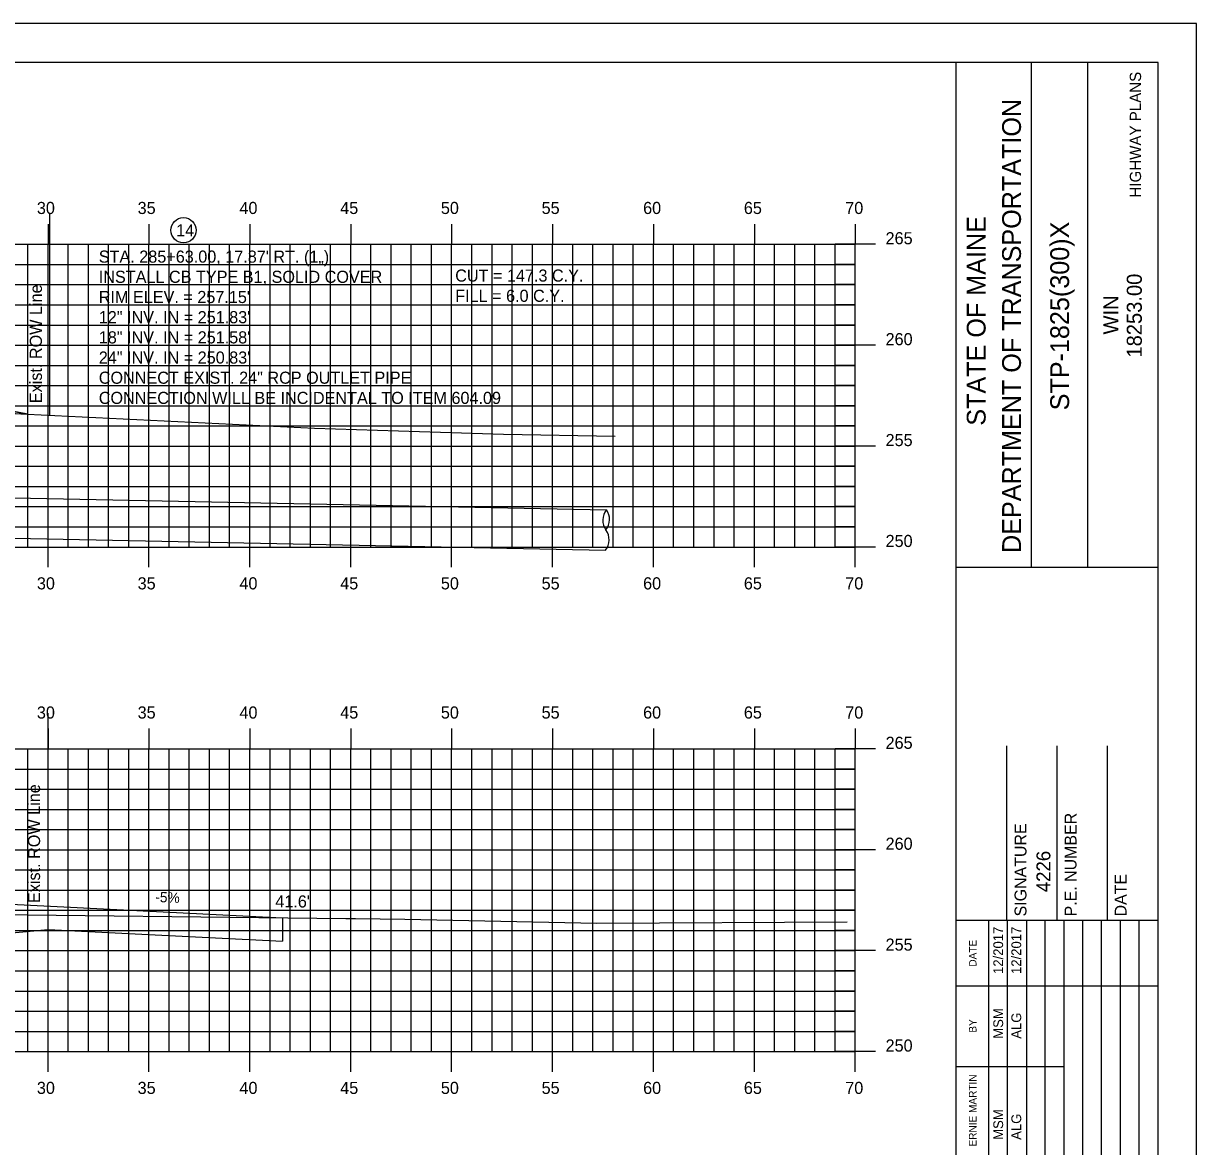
# Model space of a CAD drawing. Extents: x 856680 to 856850, y 366268 to 366378.
# Drawn here: x 856791.9 to 856850, y 366322.5 to 366378.2 of the extents above; entities that cross this region are included whole.
import ezdxf

# ---------------------------------------------------------------- set-up
doc = ezdxf.new("R2010")
doc.units = 0
for name, color, linetype in [('ANNOTATION', 7, 'Continuous'), ('BORDER', 7, 'Continuous'), ('D_Drainage_Text', 7, 'Continuous'), ('D_Roadway_Drive_Gravel_RT', 7, 'Continuous'), ('D_Roadway_Drive_SubGrade', 7, 'Continuous'), ('D_Roadway_FinishedGrade', 7, 'Continuous'), ('D_Text_Standard', 7, 'Continuous'), ('E_ROW_Line', 7, 'Continuous'), ('H_V ANNOTATION', 7, 'Continuous'), ('HIGHWAY_TITLE', 7, 'Continuous'), ('JUNK FILL', 7, 'Continuous'), ('MAJOR', 7, 'Continuous'), ('MINOR', 7, 'Continuous'), ('PLOT BOUNDARY', 7, 'Continuous'), ('S_Drainage_Culvert_Top', 7, 'Continuous'), ('S_Roadway_Centerline', 7, 'Continuous')]:
    doc.layers.add(name, color=color, linetype=linetype)

msp = doc.modelspace()

# ---------------------------------------------------------------- linework, layer by layer
at = {"layer": 'BORDER'}
for p, q in [((856848.116, 366376.236), (856688.116, 366376.236)), ((856838.116, 366271.236), (856838.116, 366376.239)), ((856841.845, 366351.234), (856841.845, 366376.234)), ((856844.64, 366351.234), (856844.64, 366376.234)), ((856848.116, 366271.236), (856848.116, 366376.236)), ((856838.117, 366351.231), (856848.116, 366351.231)), ((856840.616, 366333.739), (856840.616, 366342.387)), ((856843.116, 366333.739), (856843.116, 366342.387)), ((856845.616, 366333.739), (856845.616, 366342.387)), ((856838.116, 366333.739), (856848.116, 366333.739))]:
    msp.add_line(p, q, dxfattribs=at)
for points in [[(856839.731, 366330.489), (856839.731, 366333.739)], [(856840.664, 366316.242), (856840.664, 366333.739)], [(856841.596, 366333.739), (856841.596, 366316.242)], [(856842.527, 366316.242), (856842.527, 366333.739)], [(856843.459, 366316.242), (856843.459, 366333.739)], [(856844.391, 366316.242), (856844.391, 366333.739)], [(856845.322, 366316.242), (856845.322, 366333.739)], [(856846.254, 366316.242), (856846.254, 366333.739)], [(856847.186, 366316.242), (856847.186, 366333.739)], [(856839.732, 366316.242), (856839.732, 366333.033)], [(856838.116, 366330.489), (856848.116, 366330.489)], [(856838.116, 366326.489), (856839.732, 366326.489)], [(856839.731, 366326.489), (856843.458, 366326.489)]]:
    msp.add_lwpolyline(points, dxfattribs=at)
at = {"layer": 'D_Drainage_Text'}
msp.add_circle((856799.831, 366367.931), 0.625, dxfattribs=at)
at = {"layer": 'D_Roadway_Drive_Gravel_RT'}
for p, q in [((856787.117, 366334.751), (856804.736, 366333.87)), ((856793.116, 366333.283), (856804.736, 366332.702))]:
    msp.add_line(p, q, dxfattribs=at)
at = {"layer": 'D_Roadway_Drive_SubGrade'}
for p, q in [((856804.736, 366333.87), (856804.736, 366332.703)), ((856783.116, 366332.397), (856793.116, 366333.283))]:
    msp.add_line(p, q, dxfattribs=at)
at = {"layer": 'D_Roadway_FinishedGrade'}
msp.add_lwpolyline([(856785.533, 366360.081), (856792.116, 366358.816)], dxfattribs=at)
at = {"layer": 'E_ROW_Line'}
for p, q in [((856793.214, 366358.763), (856793.214, 366368.763)), ((856793.123, 366333.997), (856793.123, 366343.997))]:
    msp.add_line(p, q, dxfattribs=at)
at = {"layer": 'JUNK FILL'}
msp.add_lwpolyline([(856783.116, 366360.13), (856783.116, 366358.735), (856783.824, 366358.804), (856784.545, 366358.884), (856786.381, 366359.268), (856788.154, 366359.038), (856788.771, 366359.002), (856792.116, 366358.816), (856785.533, 366360.081)], close=True, dxfattribs=at)
at = {"layer": 'MAJOR'}
for p, q in [((856793.116, 366368.238), (856793.116, 366367.236)), ((856798.116, 366368.238), (856798.116, 366367.236)), ((856803.116, 366368.238), (856803.116, 366367.236)), ((856808.116, 366368.238), (856808.116, 366367.236)), ((856813.116, 366368.238), (856813.116, 366367.236)), ((856818.116, 366368.238), (856818.116, 366367.236)), ((856823.116, 366368.238), (856823.116, 366367.236)), ((856828.116, 366368.238), (856828.116, 366367.236)), ((856833.116, 366368.238), (856833.116, 366367.236)), ((856693.116, 366367.236), (856833.116, 366367.236)), ((856693.116, 366367.236), (856833.116, 366367.236)), ((856793.116, 366352.236), (856793.116, 366367.236)), ((856798.116, 366352.236), (856798.116, 366367.236)), ((856803.116, 366352.236), (856803.116, 366367.236)), ((856808.116, 366352.236), (856808.116, 366367.236)), ((856813.116, 366352.236), (856813.116, 366367.236)), ((856818.116, 366352.236), (856818.116, 366367.236)), ((856823.116, 366352.236), (856823.116, 366367.236)), ((856828.116, 366352.236), (856828.116, 366367.236)), ((856834.118, 366367.236), (856832.114, 366367.236)), ((856833.116, 366352.236), (856833.116, 366367.236)), ((856833.116, 366352.236), (856833.116, 366367.236)), ((856693.116, 366362.236), (856833.116, 366362.236)), ((856834.118, 366362.236), (856832.114, 366362.236)), ((856693.116, 366357.236), (856833.116, 366357.236)), ((856834.118, 366357.236), (856832.114, 366357.236)), ((856693.116, 366352.236), (856833.116, 366352.236)), ((856693.116, 366352.236), (856833.116, 366352.236)), ((856793.116, 366351.234), (856793.116, 366352.236)), ((856798.116, 366351.234), (856798.116, 366352.236)), ((856803.116, 366351.234), (856803.116, 366352.236)), ((856808.116, 366351.234), (856808.116, 366352.236)), ((856813.116, 366351.234), (856813.116, 366352.236)), ((856818.116, 366351.234), (856818.116, 366352.236)), ((856823.116, 366351.234), (856823.116, 366352.236)), ((856828.116, 366351.234), (856828.116, 366352.236)), ((856834.118, 366352.236), (856832.114, 366352.236)), ((856833.116, 366351.234), (856833.116, 366352.236)), ((856793.116, 366343.238), (856793.116, 366342.236)), ((856798.116, 366343.238), (856798.116, 366342.236)), ((856803.116, 366343.238), (856803.116, 366342.236)), ((856808.116, 366343.238), (856808.116, 366342.236)), ((856813.116, 366343.238), (856813.116, 366342.236)), ((856818.116, 366343.238), (856818.116, 366342.236)), ((856823.116, 366343.238), (856823.116, 366342.236)), ((856828.116, 366343.238), (856828.116, 366342.236)), ((856833.116, 366343.238), (856833.116, 366342.236)), ((856693.116, 366342.236), (856833.116, 366342.236)), ((856693.116, 366342.236), (856833.116, 366342.236)), ((856793.116, 366327.236), (856793.116, 366342.236)), ((856798.116, 366327.236), (856798.116, 366342.236)), ((856803.116, 366327.236), (856803.116, 366342.236)), ((856808.116, 366327.236), (856808.116, 366342.236)), ((856813.116, 366327.236), (856813.116, 366342.236)), ((856818.116, 366327.236), (856818.116, 366342.236)), ((856823.116, 366327.236), (856823.116, 366342.236)), ((856828.116, 366327.236), (856828.116, 366342.236)), ((856834.118, 366342.236), (856832.114, 366342.236)), ((856833.116, 366327.236), (856833.116, 366342.236)), ((856833.116, 366327.236), (856833.116, 366342.236)), ((856693.116, 366337.236), (856833.116, 366337.236)), ((856834.118, 366337.236), (856832.114, 366337.236)), ((856693.116, 366332.236), (856833.116, 366332.236)), ((856834.118, 366332.236), (856832.114, 366332.236)), ((856693.116, 366327.236), (856833.116, 366327.236)), ((856693.116, 366327.236), (856833.116, 366327.236)), ((856793.116, 366326.234), (856793.116, 366327.236)), ((856798.116, 366326.234), (856798.116, 366327.236)), ((856803.116, 366326.234), (856803.116, 366327.236)), ((856808.116, 366326.234), (856808.116, 366327.236)), ((856813.116, 366326.234), (856813.116, 366327.236)), ((856818.116, 366326.234), (856818.116, 366327.236)), ((856823.116, 366326.234), (856823.116, 366327.236)), ((856828.116, 366326.234), (856828.116, 366327.236)), ((856834.118, 366327.236), (856832.114, 366327.236)), ((856833.116, 366326.234), (856833.116, 366327.236))]:
    msp.add_line(p, q, dxfattribs=at)
at = {"layer": 'MINOR'}
for p, q in [((856792.116, 366352.236), (856792.116, 366367.236)), ((856794.116, 366352.236), (856794.116, 366367.236)), ((856795.116, 366352.236), (856795.116, 366367.236)), ((856796.116, 366352.236), (856796.116, 366367.236)), ((856797.116, 366352.236), (856797.116, 366367.236)), ((856799.116, 366352.236), (856799.116, 366367.236)), ((856800.116, 366352.236), (856800.116, 366367.236)), ((856801.116, 366352.236), (856801.116, 366367.236)), ((856802.116, 366352.236), (856802.116, 366367.236)), ((856804.116, 366352.236), (856804.116, 366367.236)), ((856805.116, 366352.236), (856805.116, 366367.236)), ((856806.116, 366352.236), (856806.116, 366367.236)), ((856807.116, 366352.236), (856807.116, 366367.236)), ((856809.116, 366352.236), (856809.116, 366367.236)), ((856810.116, 366352.236), (856810.116, 366367.236)), ((856811.116, 366352.236), (856811.116, 366367.236)), ((856812.116, 366352.236), (856812.116, 366367.236)), ((856814.116, 366352.236), (856814.116, 366367.236)), ((856815.116, 366352.236), (856815.116, 366367.236)), ((856816.116, 366352.236), (856816.116, 366367.236)), ((856817.116, 366352.236), (856817.116, 366367.236)), ((856819.116, 366352.236), (856819.116, 366367.236)), ((856820.116, 366352.236), (856820.116, 366367.236)), ((856821.116, 366352.236), (856821.116, 366367.236)), ((856822.116, 366352.236), (856822.116, 366367.236)), ((856824.116, 366352.236), (856824.116, 366367.236)), ((856825.116, 366352.236), (856825.116, 366367.236)), ((856826.116, 366352.236), (856826.116, 366367.236)), ((856827.116, 366352.236), (856827.116, 366367.236)), ((856829.116, 366352.236), (856829.116, 366367.236)), ((856830.116, 366352.236), (856830.116, 366367.236)), ((856831.116, 366352.236), (856831.116, 366367.236)), ((856832.116, 366352.236), (856832.116, 366367.236)), ((856693.116, 366366.236), (856833.116, 366366.236)), ((856833.116, 366366.236), (856832.114, 366366.236)), ((856693.116, 366365.236), (856833.116, 366365.236)), ((856833.116, 366365.236), (856832.114, 366365.236)), ((856693.116, 366364.236), (856833.116, 366364.236)), ((856833.116, 366364.236), (856832.114, 366364.236)), ((856693.116, 366363.236), (856833.116, 366363.236)), ((856833.116, 366363.236), (856832.114, 366363.236)), ((856693.116, 366361.236), (856833.116, 366361.236)), ((856833.116, 366361.236), (856832.114, 366361.236)), ((856693.116, 366360.236), (856833.116, 366360.236)), ((856833.116, 366360.236), (856832.114, 366360.236)), ((856693.116, 366359.236), (856833.116, 366359.236)), ((856833.116, 366359.236), (856832.114, 366359.236)), ((856693.116, 366358.236), (856833.116, 366358.236)), ((856833.116, 366358.236), (856832.114, 366358.236)), ((856693.116, 366356.236), (856833.116, 366356.236)), ((856833.116, 366356.236), (856832.114, 366356.236)), ((856693.116, 366355.236), (856833.116, 366355.236)), ((856833.116, 366355.236), (856832.114, 366355.236)), ((856693.116, 366354.236), (856833.116, 366354.236)), ((856833.116, 366354.236), (856832.114, 366354.236)), ((856693.116, 366353.236), (856833.116, 366353.236)), ((856833.116, 366353.236), (856832.114, 366353.236)), ((856792.116, 366327.236), (856792.116, 366342.236)), ((856794.116, 366327.236), (856794.116, 366342.236)), ((856795.116, 366327.236), (856795.116, 366342.236)), ((856796.116, 366327.236), (856796.116, 366342.236)), ((856797.116, 366327.236), (856797.116, 366342.236)), ((856799.116, 366327.236), (856799.116, 366342.236)), ((856800.116, 366327.236), (856800.116, 366342.236)), ((856801.116, 366327.236), (856801.116, 366342.236)), ((856802.116, 366327.236), (856802.116, 366342.236)), ((856804.116, 366327.236), (856804.116, 366342.236)), ((856805.116, 366327.236), (856805.116, 366342.236)), ((856806.116, 366327.236), (856806.116, 366342.236)), ((856807.116, 366327.236), (856807.116, 366342.236)), ((856809.116, 366327.236), (856809.116, 366342.236)), ((856810.116, 366327.236), (856810.116, 366342.236)), ((856811.116, 366327.236), (856811.116, 366342.236)), ((856812.116, 366327.236), (856812.116, 366342.236)), ((856814.116, 366327.236), (856814.116, 366342.236)), ((856815.116, 366327.236), (856815.116, 366342.236)), ((856816.116, 366327.236), (856816.116, 366342.236)), ((856817.116, 366327.236), (856817.116, 366342.236)), ((856819.116, 366327.236), (856819.116, 366342.236)), ((856820.116, 366327.236), (856820.116, 366342.236)), ((856821.116, 366327.236), (856821.116, 366342.236)), ((856822.116, 366327.236), (856822.116, 366342.236)), ((856824.116, 366327.236), (856824.116, 366342.236)), ((856825.116, 366327.236), (856825.116, 366342.236)), ((856826.116, 366327.236), (856826.116, 366342.236)), ((856827.116, 366327.236), (856827.116, 366342.236)), ((856829.116, 366327.236), (856829.116, 366342.236)), ((856830.116, 366327.236), (856830.116, 366342.236)), ((856831.116, 366327.236), (856831.116, 366342.236)), ((856832.116, 366327.236), (856832.116, 366342.236)), ((856693.116, 366341.236), (856833.116, 366341.236)), ((856833.116, 366341.236), (856832.114, 366341.236)), ((856693.116, 366340.236), (856833.116, 366340.236)), ((856833.116, 366340.236), (856832.114, 366340.236)), ((856693.116, 366339.236), (856833.116, 366339.236)), ((856833.116, 366339.236), (856832.114, 366339.236)), ((856693.116, 366338.236), (856833.116, 366338.236)), ((856833.116, 366338.236), (856832.114, 366338.236)), ((856693.116, 366336.236), (856833.116, 366336.236)), ((856833.116, 366336.236), (856832.114, 366336.236)), ((856693.116, 366335.236), (856833.116, 366335.236)), ((856833.116, 366335.236), (856832.114, 366335.236)), ((856693.116, 366334.236), (856833.116, 366334.236)), ((856833.116, 366334.236), (856832.114, 366334.236)), ((856693.116, 366333.236), (856833.116, 366333.236)), ((856833.116, 366333.236), (856832.114, 366333.236)), ((856693.116, 366331.236), (856833.116, 366331.236)), ((856833.116, 366331.236), (856832.114, 366331.236)), ((856693.116, 366330.236), (856833.116, 366330.236)), ((856833.116, 366330.236), (856832.114, 366330.236)), ((856693.116, 366329.236), (856833.116, 366329.236)), ((856833.116, 366329.236), (856832.114, 366329.236)), ((856693.116, 366328.236), (856833.116, 366328.236)), ((856833.116, 366328.236), (856832.114, 366328.236))]:
    msp.add_line(p, q, dxfattribs=at)
at = {"layer": 'PLOT BOUNDARY'}
msp.add_lwpolyline([(856680.023, 366268.177), (856850.023, 366268.177), (856850.023, 366378.177), (856680.023, 366378.177)], close=True, dxfattribs=at)
at = {"layer": 'S_Drainage_Culvert_Top'}
for p, q in [((856783.873, 366354.819), (856820.78, 366354.081)), ((856783.873, 366352.818), (856820.74, 366352.081))]:
    msp.add_line(p, q, dxfattribs=at)
for centre, start, end in [((856821.437, 366353.567), 141.98434, 215.72413), ((856820.104, 366353.594), 321.98434, 35.72413), ((856820.084, 366352.594), 321.98434, 35.72413)]:
    msp.add_arc(centre, 0.833, start, end, dxfattribs=at)
at = {"layer": 'S_Roadway_Centerline'}
for points in [[(856791.431, 366358.849), (856806.317, 366358.133), (856815.684, 366357.834), (856821.222, 366357.728)], [(856787.76, 366334.057), (856807.868, 366333.829), (856808.093, 366333.826), (856808.204, 366333.826), (856808.258, 366333.826), (856808.306, 366333.826), (856808.328, 366333.826), (856808.353, 366333.826), (856810.804, 366333.794), (856820.314, 366333.599), (856832.717, 366333.667)]]:
    msp.add_lwpolyline(points, dxfattribs=at)

# ---------------------------------------------------------------- texts
at = {"layer": 'ANNOTATION'}
for s, p in [('CUT = 147.3 C.Y.', (856813.292, 366365.386)), ('FILL = 6.0 C.Y.', (856813.292, 366364.384))]:
    msp.add_text(s, height=0.6, dxfattribs=at).set_placement(p)
for s, height, rotation, p in [('4226', 0.69, 90, (856842.781, 366335.13)), ('-5%', 0.51, 357.70939, (856798.422, 366334.648))]:
    msp.add_text(s, height=height, rotation=rotation, dxfattribs=at).set_placement(p)
at = {"layer": 'BORDER'}
for s, height, p in [('DEPARTMENT OF TRANSPORTATION', 0.93176, (856841.323, 366351.942)), ('STATE OF MAINE', 0.93176, (856839.572, 366358.248)), ('STP-1825(300)X', 0.93176, (856843.708, 366359.008)), ('18253.00', 0.7453, (856847.312, 366361.623)), ('WIN', 0.7453, (856846.153, 366362.766)), ('P.E. NUMBER', 0.59055, (856844.077, 366333.932)), ('SIGNATURE', 0.5906, (856841.597, 366333.932)), ('DATE', 0.5906, (856846.558, 366333.932)), ('12/2017', 0.4845, (856840.439, 366331.081)), ('12/2017', 0.4845, (856841.334, 366331.081)), ('DATE', 0.3714, (856839.121, 366331.445)), ('MSM', 0.4845, (856840.439, 366327.872)), ('ALG', 0.4845, (856841.334, 366327.872)), ('BY', 0.3714, (856839.121, 366328.174)), ('ERNIE MARTIN', 0.37275, (856839.121, 366322.531)), ('MSM', 0.4845, (856840.439, 366322.863)), ('ALG', 0.4845, (856841.334, 366322.863))]:
    msp.add_text(s, height=height, rotation=90, dxfattribs=at).set_placement(p)
at = {"layer": 'D_Drainage_Text'}
for s, p in [("STA. 285+63.00, 17.87' RT. (1„)", (856795.632, 366366.325)), ('INSTALL CB TYPE B1, SOLID COVER', (856795.632, 366365.325)), ("RIM ELEV. = 257.15'", (856795.632, 366364.325)), ('12" INV. IN = 251.83\'', (856795.632, 366363.325)), ('18" INV. IN = 251.58\'', (856795.632, 366362.325)), ('24" INV. IN = 250.83\'', (856795.632, 366361.325)), ('CONNECT EXIST. 24" RCP OUTLET PIPE', (856795.632, 366360.325)), ('CONNECTION WILL BE INCIDENTAL TO ITEM 604.09', (856795.632, 366359.325))]:
    msp.add_text(s, height=0.6, dxfattribs=at).set_placement(p)
at = {"layer": 'D_Text_Standard'}
msp.add_text("41.6'", height=0.6, dxfattribs=at).set_placement((856804.378, 366334.376))
at = {"layer": 'E_ROW_Line'}
for p in [(856792.814, 366359.363), (856792.723, 366334.597)]:
    msp.add_text('Exist. ROW Line', height=0.6, rotation=90, dxfattribs=at).set_placement(p)
at = {"layer": 'H_V ANNOTATION'}
for s, p in [('30', (856792.565, 366368.736)), ('35', (856797.557, 366368.736)), ('40', (856802.602, 366368.736)), ('45', (856807.594, 366368.736)), ('50', (856812.581, 366368.736)), ('55', (856817.573, 366368.736)), ('60', (856822.602, 366368.736)), ('65', (856827.594, 366368.736)), ('70', (856832.618, 366368.736)), ('14', (856799.467, 366367.627)), ('265', (856834.616, 366367.236)), ('260', (856834.616, 366362.236)), ('255', (856834.616, 366357.236)), ('250', (856834.616, 366352.236)), ('30', (856792.565, 366350.136)), ('35', (856797.557, 366350.136)), ('40', (856802.602, 366350.136)), ('45', (856807.594, 366350.136)), ('50', (856812.581, 366350.136)), ('55', (856817.573, 366350.136)), ('60', (856822.602, 366350.136)), ('65', (856827.594, 366350.136)), ('70', (856832.618, 366350.136)), ('30', (856792.565, 366343.736)), ('35', (856797.557, 366343.736)), ('40', (856802.602, 366343.736)), ('45', (856807.594, 366343.736)), ('50', (856812.581, 366343.736)), ('55', (856817.573, 366343.736)), ('60', (856822.602, 366343.736)), ('65', (856827.594, 366343.736)), ('70', (856832.618, 366343.736)), ('265', (856834.616, 366342.236)), ('260', (856834.616, 366337.236)), ('255', (856834.616, 366332.236)), ('250', (856834.616, 366327.236)), ('30', (856792.565, 366325.136)), ('35', (856797.557, 366325.136)), ('40', (856802.602, 366325.136)), ('45', (856807.594, 366325.136)), ('50', (856812.581, 366325.136)), ('55', (856817.573, 366325.136)), ('60', (856822.602, 366325.136)), ('65', (856827.594, 366325.136)), ('70', (856832.618, 366325.136))]:
    msp.add_text(s, height=0.6, dxfattribs=at).set_placement(p)
at = {"layer": 'HIGHWAY_TITLE'}
msp.add_text('HIGHWAY PLANS', height=0.55901, rotation=90, dxfattribs=at).set_placement((856847.275, 366369.552))

doc.saveas('drawing.dxf')
